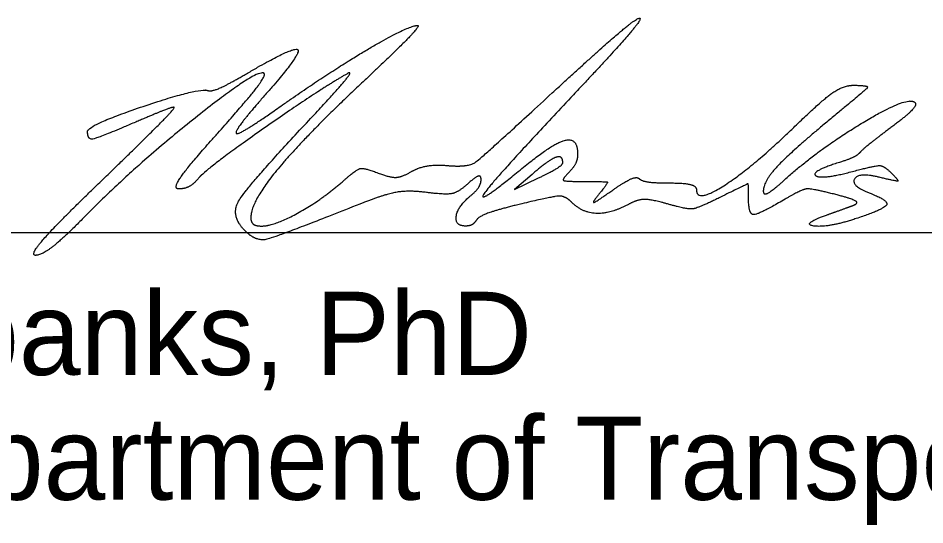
# Model space of a CAD drawing. Extents: x -7.5 to 53.5, y 0 to 22.
# Drawn here: x 26.636 to 28.162, y 6.077 to 6.93 of the extents above; entities that cross this region are included whole.
import ezdxf

# ---------------------------------------------------------------- set-up
doc = ezdxf.new("R2010")
doc.units = 0
doc.layers.add('SH_Data', color=7, linetype='Continuous')
doc.layers.add('SH_Text', color=7, linetype='Continuous')

msp = doc.modelspace()

# ---------------------------------------------------------------- linework, layer by layer
at = {"layer": 'SH_Data'}
msp.add_line((25.5763, 6.5695), (29.0763, 6.5695), dxfattribs=at)
at = {"layer": 'SH_Text'}
for p, q in [((27.5529, 6.6867), (27.5529, 6.6867)), ((26.7758, 6.6556), (26.7758, 6.6556))]:
    msp.add_line(p, q, dxfattribs=at)
msp.add_lwpolyline([(27.5012, 6.667), (27.4717, 6.6414), (27.5123, 6.6611)], dxfattribs=at)
for points in [[(27.5353, 6.8042), (27.6103, 6.8733), (27.6764, 6.9299), (27.6821, 6.93)], [(27.6821, 6.93), (27.6878, 6.93), (27.6358, 6.8699), (27.5665, 6.7963)], [(27.0811, 6.7838), (27.1616, 6.8404), (27.2929, 6.9176), (27.3086, 6.9176)], [(27.3086, 6.9176), (27.3135, 6.9176), (27.2722, 6.875), (27.2168, 6.8229)], [(27.0221, 6.8373), (27.1009, 6.8834), (27.1131, 6.8702), (27.0539, 6.8029)], [(27.0502, 6.837), (27.0406, 6.8466), (26.8308, 6.6797), (26.7529, 6.6004)], [(26.9565, 6.808), (26.962, 6.8062), (26.9916, 6.8194), (27.0221, 6.8373)], [(26.9724, 6.7366), (27.0186, 6.7884), (27.0537, 6.8335), (27.0502, 6.837)], [(27.1253, 6.7576), (27.1714, 6.8069), (27.2007, 6.8424), (27.1904, 6.8366)], [(27.1904, 6.8366), (27.1414, 6.8088), (26.9531, 6.6766), (26.9398, 6.6606)], [(27.2168, 6.8229), (27.1172, 6.7292), (27.0279, 6.621), (27.0279, 6.5941)], [(26.7531, 6.7395), (26.7534, 6.75), (26.9407, 6.8132), (26.9565, 6.808)], [(27.9436, 6.7479), (27.9888, 6.7917), (28.0259, 6.8174), (28.0436, 6.817)], [(28.0436, 6.817), (28.0679, 6.8166), (28.0641, 6.8102), (28.0154, 6.7702)], [(27.0539, 6.8029), (27.0259, 6.7711), (27.0029, 6.7414), (27.0029, 6.7369)], [(27.3603, 6.6818), (27.3938, 6.679), (27.4173, 6.6954), (27.5353, 6.8042)], [(27.5665, 6.7963), (27.4369, 6.6587), (27.4049, 6.6115), (27.487, 6.6792)], [(26.7758, 6.6556), (26.8468, 6.7241), (26.9021, 6.7801), (26.8987, 6.7801)], [(26.8987, 6.7801), (26.8953, 6.7801), (26.8663, 6.7689), (26.8342, 6.7551)], [(27.0029, 6.7369), (27.0029, 6.7325), (27.0381, 6.7536), (27.0811, 6.7838)], [(27.9248, 6.6567), (27.9784, 6.7055), (28.1254, 6.7955), (28.1423, 6.7899)], [(28.1423, 6.7899), (28.1507, 6.7871), (28.1354, 6.7684), (28.1083, 6.7482)], [(28.0154, 6.7702), (27.9414, 6.7092), (27.8904, 6.6557), (27.8904, 6.6389)], [(26.8342, 6.7551), (26.7716, 6.7283), (26.7528, 6.7247), (26.7531, 6.7395)], [(27.0182, 6.572), (26.993, 6.5972), (27.0219, 6.6473), (27.1253, 6.7576)], [(27.7779, 6.6411), (27.7779, 6.6183), (27.8732, 6.6797), (27.9436, 6.7479)], [(28.1083, 6.7482), (28.0813, 6.728), (28.0564, 6.708), (28.0529, 6.7037)], [(26.9065, 6.6426), (26.8962, 6.6426), (26.9251, 6.6839), (26.9724, 6.7366)], [(27.487, 6.6792), (27.5354, 6.7191), (27.5779, 6.7295), (27.5779, 6.7014)], [(27.5779, 6.7014), (27.5779, 6.6924), (27.5712, 6.6784), (27.5629, 6.6701)], [(28.0529, 6.7037), (28.0495, 6.6995), (28.034, 6.692), (28.0186, 6.6872)], [(27.5529, 6.6867), (27.5529, 6.7002), (27.5288, 6.691), (27.5012, 6.667)], [(27.5123, 6.6611), (27.5347, 6.6719), (27.5529, 6.6834), (27.5529, 6.6867)], [(28.0186, 6.6872), (27.969, 6.6717), (27.9885, 6.6581), (28.0404, 6.6719)], [(27.1854, 6.6576), (27.2057, 6.6756), (27.2186, 6.6783), (27.2423, 6.6693)], [(27.2423, 6.6693), (27.2625, 6.6616), (27.2813, 6.6623), (27.2973, 6.6713)], [(27.2973, 6.6713), (27.3107, 6.6789), (27.3391, 6.6836), (27.3603, 6.6818)], [(27.5629, 6.6701), (27.5513, 6.6584), (27.5572, 6.6551), (27.5895, 6.6551)], [(28.0404, 6.6719), (28.0787, 6.6821), (28.094, 6.6815), (28.106, 6.6693)], [(28.106, 6.6693), (28.1187, 6.6564), (28.1151, 6.655), (28.0873, 6.6618)], [(26.6654, 6.5308), (26.6551, 6.531), (26.7048, 6.5872), (26.7758, 6.6556)], [(26.9398, 6.6606), (26.9316, 6.6507), (26.9166, 6.6426), (26.9065, 6.6426)], [(27.046, 6.5801), (27.0677, 6.5801), (27.149, 6.6253), (27.1854, 6.6576)], [(27.4154, 6.6586), (27.4154, 6.6657), (27.4053, 6.6623), (27.3929, 6.6511)], [(27.3967, 6.6301), (27.407, 6.6387), (27.4154, 6.6515), (27.4154, 6.6586)], [(27.5895, 6.6551), (27.627, 6.6551), (27.6294, 6.6531), (27.6138, 6.6337)], [(27.6356, 6.6396), (27.657, 6.6546), (27.6777, 6.6637), (27.6816, 6.6597)], [(27.6816, 6.6597), (27.6856, 6.6558), (27.7088, 6.6526), (27.7334, 6.6526)], [(27.8904, 6.6389), (27.8904, 6.6315), (27.9059, 6.6395), (27.9248, 6.6567)], [(28.0873, 6.6618), (28.0506, 6.6709), (28.0373, 6.6478), (28.0717, 6.6346)], [(27.3234, 6.6366), (27.2941, 6.6404), (27.2543, 6.6339), (27.2178, 6.6195)], [(27.3929, 6.6511), (27.3772, 6.6369), (27.3559, 6.6325), (27.3234, 6.6366)], [(27.6138, 6.6337), (27.6018, 6.6187), (27.6083, 6.6205), (27.6356, 6.6396)], [(27.7334, 6.6526), (27.7579, 6.6526), (27.7779, 6.6474), (27.7779, 6.6411)], [(27.8654, 6.6285), (27.8654, 6.6514), (27.8644, 6.6514), (27.8182, 6.6286)], [(28.0106, 6.6335), (27.9717, 6.6434), (27.955, 6.6418), (27.9274, 6.6255)], [(27.3897, 6.5801), (27.3713, 6.5801), (27.3759, 6.6129), (27.3967, 6.6301)], [(27.5683, 6.6197), (27.5572, 6.6308), (27.5372, 6.6303), (27.484, 6.6176)], [(27.7291, 6.6173), (27.7023, 6.625), (27.6791, 6.6249), (27.6647, 6.6172)], [(27.8182, 6.6286), (27.7808, 6.6101), (27.7623, 6.6078), (27.7291, 6.6173)], [(27.9274, 6.6255), (27.8823, 6.5989), (27.8654, 6.5997), (27.8654, 6.6285)], [(28.0404, 6.6143), (28.0518, 6.6185), (28.0401, 6.626), (28.0106, 6.6335)], [(28.0717, 6.6346), (28.1022, 6.6229), (28.0933, 6.608), (28.0466, 6.5926)], [(27.2178, 6.6195), (27.0717, 6.5618), (27.0367, 6.5535), (27.0182, 6.572)], [(27.484, 6.6176), (27.4457, 6.6084), (27.4114, 6.5962), (27.4079, 6.5905)], [(27.6647, 6.6172), (27.6339, 6.6007), (27.5861, 6.602), (27.5683, 6.6197)], [(27.9967, 6.5986), (28.0104, 6.6035), (28.0301, 6.6106), (28.0404, 6.6143)], [(26.7529, 6.6004), (26.7151, 6.5619), (26.6757, 6.5306), (26.6654, 6.5308)], [(27.0279, 6.5941), (27.0279, 6.5864), (27.0361, 6.5801), (27.046, 6.5801)], [(28.0466, 6.5926), (28, 6.5772), (27.9526, 6.5829), (27.9967, 6.5986)], [(27.4079, 6.5905), (27.4043, 6.5848), (27.3962, 6.5801), (27.3897, 6.5801)]]:
    msp.add_open_spline(points, degree=2, dxfattribs=at)

# ---------------------------------------------------------------- texts
for s, p in [('Jack Marchbanks, PhD', (25.5763, 6.3295)), ('Director, Department of Transportation', (25.5763, 6.1195))]:
    msp.add_text(s, height=0.14, dxfattribs=at).set_placement(p)

doc.saveas('drawing.dxf')
